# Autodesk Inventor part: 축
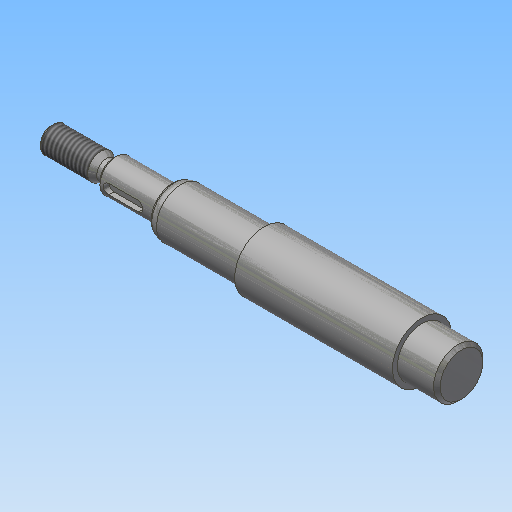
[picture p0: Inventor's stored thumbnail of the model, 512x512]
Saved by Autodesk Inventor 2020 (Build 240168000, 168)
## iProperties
Created: 2015-11
Part Number: 축
Material: 강철, 연강
Document SubType Name: Modeling
Designer: mduedu
Density: 1 g/cm^3
Appearance: 강철
Author: mduedu
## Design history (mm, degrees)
sketch "스케치1"
  geometry: L1 (-89, 0)-(89, 0); L2 (-89, 0)-(-89, 4); L3 (-89, 4)-(-73.732, 4); L4 (-73.732, 4)-(-72, 3); L5 (-72, 3)-(-70, 3); L6 (-70, 3)-(-70, 5); L7 (-70, 5)-(-52, 5); L8 (-52, 5)-(-52, 6.55); L9 (-50.355, 7.5)-(-24, 7.5); L10 (-24, 7.5)-(-24, 9); L11 (0, 0)-(0, 9); L12 (89, 4)-(73.732, 4); L13 (73.732, 4)-(72, 3); L14 (72, 3)-(70, 3); L15 (70, 3)-(70, 5); L16 (70, 5)-(52, 5); L17 (24, 7.5)-(24, 9); L18 (89, 0)-(89, 4); L19 (-24, 9)-(24, 9); L20 (-52, 6.55)-(-50.355, 7.5); L21 (50.355, 7.5)-(24, 7.5); L22 (52, 6.55)-(50.355, 7.5); L23 (52, 5)-(52, 6.55); 1 further point
  constraints: 46 end point, 10 symmetric about line, 6 perpendicular, 5 parallel, 2 midpoint, 1 coincident, 1 horizontal
  dimensions: "d0" = 178 distance of L1.start L1.end (derived); "d1" = 8 diameter of L3 L1; "d2" = 30 deg angle of L4 L5; "d3" = 6 diameter of L5 L1; "d4" = 10 diameter of L7 L1; "d5" = 15 diameter of L9 L1; "d6" = 18 diameter of L19 L1; "d8" = 18 distance of L6.end L7.end; "d9" = 48 distance of L10.end L17.end; "d10" = 2 distance of L4.end L5.end; "d11" = 17 distance from line of L4.end L2; "d16" = 13.1 diameter of L8.end L1; "d17" = 30 deg angle of L20 L9; "d18" = 28 distance between parallel lines of L10 L8
revolve "회전1" sketch "스케치1" stored, may be unused: angle "d12" = 90 deg
chamfer "모따기1" distance "d13" = 1; stored, may be unused: second distance "d14" = 2, angle "d15" = 45 deg
fillet "모깎기1" dims "d19" = 4, "d20" = 0.5
node "작업 평면1"
sketch "스케치2" dims "d23" = 12
  geometry: L1 (-5.5, 1.5)-(3.5, 1.5); L2 (3.5, 1.5)-(3.5, -1.5); L3 (3.5, -1.5)-(-5.5, -1.5); L4 (-5.5, -1.5)-(-5.5, 1.5); L5 (-9, -4)-(-9, 4) reference; 3 further points
  constraints: 8 end point, 2 midpoint, 2 parallel, 2 vertical alignment, 1 horizontal, 1 perpendicular, 4 other
  dimensions: "d21" = 3 distance between parallel lines of L3 L1; "d24" = 2 dimension on L5
extrude "돌출1" cut sketch "스케치2" distance "d25" = 1.8; taper "d26" = 0 deg
feature "스레드1" dims "d27" = 10, "d28" = 0
feature "스레드2" dims "d29" = 10, "d30" = 0
chamfer "모따기2" distance "d31" = 1; stored, may be unused: second distance "d32" = 2, angle "d33" = 45 deg
node "작업 평면2"
sketch "스케치3"
  geometry: C1 r 7.5 at (0, 0) reference; 1 further point
extrude "돌출2" cut sketch "스케치3" extent not by distance; stored distance "d36" = 10; taper "d37" = 0 deg
chamfer "모따기3" distance "d38" = 1; stored, may be unused: second distance "d39" = 2, angle "d40" = 45 deg
node "솔리드1"
mirror "대칭1"
node "절단 모서리 투영1"
other parameters: "d35" = 12
